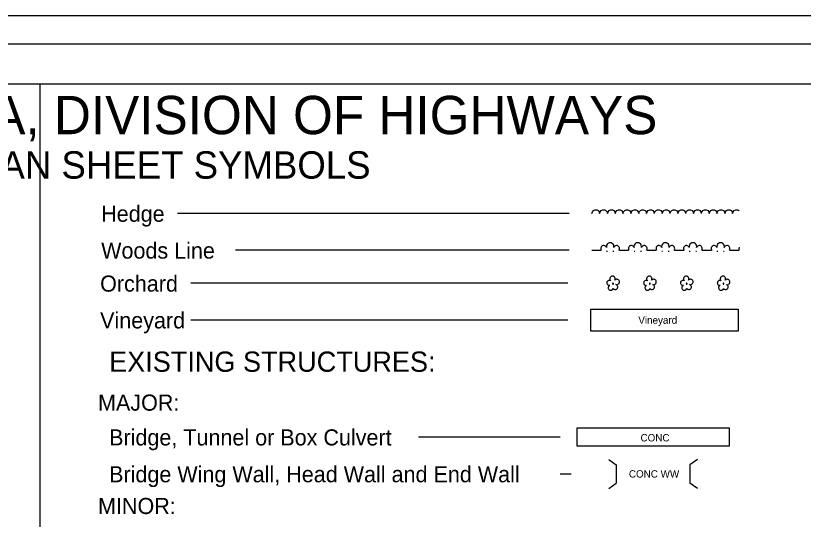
# Model space of a CAD drawing. Extents: x 811508 to 813252, y 647626 to 648754.
# Drawn here: x 812366.5 to 812809.2, y 648471 to 648754 of the extents above; entities that cross this region are included whole.
import ezdxf

# ---------------------------------------------------------------- set-up
doc = ezdxf.new("R2010")
doc.units = 0
for name, color, linetype in [('Sheet Cutting Line CELL', 7, 'Continuous'), ('Sheet Plot Border Inside CELL', 7, 'Continuous'), ('Sheet Plot Border Outside CELL', 7, 'Continuous'), ('Sheet_Plan', 7, 'Continuous'), ('Sheet_Symbology', 7, 'Continuous'), ('z - Construction', 7, 'Continuous')]:
    doc.layers.add(name, color=color, linetype=linetype)

msp = doc.modelspace()

# ---------------------------------------------------------------- linework, layer by layer
at = {"layer": 'Sheet Cutting Line CELL'}
msp.add_line((813217.6, 648737.99), (811533.6, 648737.99), dxfattribs=at)
at = {"layer": 'Sheet Plot Border Inside CELL'}
msp.add_lwpolyline([(811546.6, 647660.44), (813213.1, 647660.44), (813213.1, 648715.54), (811546.6, 648715.54)], close=True, dxfattribs=at)
at = {"layer": 'Sheet Plot Border Outside CELL'}
msp.add_lwpolyline([(811533.6, 647637.99), (813217.6, 647637.99), (813217.6, 648737.99), (811533.6, 648737.99)], close=True, dxfattribs=at)
at = {"layer": 'Sheet_Plan'}
msp.add_line((813213.53, 648715.54), (811546.6, 648715.54), dxfattribs=at)
at = {"layer": 'Sheet_Symbology'}
for p, q in [((812677.52, 648642.89), (812457.4, 648642.89)), ((812690.35, 648642.89), (812690.66, 648643.87)), ((812690.66, 648643.87), (812691.28, 648644.55)), ((812691.28, 648644.55), (812692.11, 648645.01)), ((812692.11, 648645.01), (812693.09, 648645.01)), ((812693.09, 648645.01), (812693.92, 648644.5)), ((812693.92, 648644.5), (812694.49, 648643.82)), ((812694.49, 648643.82), (812694.7, 648642.94)), ((812694.75, 648642.89), (812695.06, 648643.87)), ((812695.06, 648643.87), (812695.68, 648644.55)), ((812695.68, 648644.55), (812696.51, 648645.01)), ((812696.51, 648645.01), (812697.49, 648645.01)), ((812697.49, 648645.01), (812698.32, 648644.5)), ((812698.32, 648644.5), (812698.89, 648643.82)), ((812698.89, 648643.82), (812699.09, 648642.94)), ((812699.15, 648642.89), (812699.46, 648643.87)), ((812699.46, 648643.87), (812700.08, 648644.55)), ((812700.08, 648644.55), (812700.9, 648645.01)), ((812700.9, 648645.01), (812701.89, 648645.01)), ((812701.89, 648645.01), (812702.72, 648644.5)), ((812702.72, 648644.5), (812703.29, 648643.82)), ((812703.29, 648643.82), (812703.49, 648642.94)), ((812703.54, 648642.89), (812703.85, 648643.87)), ((812703.85, 648643.87), (812704.48, 648644.55)), ((812704.48, 648644.55), (812705.3, 648645.01)), ((812705.3, 648645.01), (812706.29, 648645.01)), ((812706.29, 648645.01), (812707.11, 648644.5)), ((812707.11, 648644.5), (812707.68, 648643.82)), ((812707.68, 648643.82), (812707.89, 648642.94)), ((812707.94, 648642.89), (812708.25, 648643.87)), ((812708.25, 648643.87), (812708.87, 648644.55)), ((812708.87, 648644.55), (812709.7, 648645.01)), ((812709.7, 648645.01), (812710.69, 648645.01)), ((812710.69, 648645.01), (812711.51, 648644.5)), ((812711.51, 648644.5), (812712.08, 648643.82)), ((812712.08, 648643.82), (812712.29, 648642.94)), ((812712.34, 648642.89), (812712.65, 648643.87)), ((812712.65, 648643.87), (812713.27, 648644.55)), ((812713.27, 648644.55), (812714.1, 648645.01)), ((812714.1, 648645.01), (812715.08, 648645.01)), ((812715.08, 648645.01), (812715.91, 648644.5)), ((812715.91, 648644.5), (812716.48, 648643.82)), ((812716.48, 648643.82), (812716.69, 648642.94)), ((812716.74, 648642.89), (812717.05, 648643.87)), ((812717.05, 648643.87), (812717.67, 648644.55)), ((812717.67, 648644.55), (812718.5, 648645.01)), ((812718.5, 648645.01), (812719.48, 648645.01)), ((812719.48, 648645.01), (812720.31, 648644.5)), ((812720.31, 648644.5), (812720.88, 648643.82)), ((812720.88, 648643.82), (812721.09, 648642.94)), ((812721.14, 648642.89), (812721.45, 648643.87)), ((812721.45, 648643.87), (812722.07, 648644.55)), ((812722.07, 648644.55), (812722.9, 648645.01)), ((812722.9, 648645.01), (812723.88, 648645.01)), ((812723.88, 648645.01), (812724.71, 648644.5)), ((812724.71, 648644.5), (812725.28, 648643.82)), ((812725.28, 648643.82), (812725.49, 648642.94)), ((812725.54, 648642.89), (812725.85, 648643.87)), ((812725.85, 648643.87), (812726.47, 648644.55)), ((812726.47, 648644.55), (812727.3, 648645.01)), ((812727.3, 648645.01), (812728.28, 648645.01)), ((812728.28, 648645.01), (812729.11, 648644.5)), ((812729.11, 648644.5), (812729.68, 648643.82)), ((812729.68, 648643.82), (812729.88, 648642.94)), ((812729.94, 648642.89), (812730.25, 648643.87)), ((812730.25, 648643.87), (812730.87, 648644.55)), ((812730.87, 648644.55), (812731.7, 648645.01)), ((812731.7, 648645.01), (812732.68, 648645.01)), ((812732.68, 648645.01), (812733.51, 648644.5)), ((812733.51, 648644.5), (812734.08, 648643.82)), ((812734.08, 648643.82), (812734.28, 648642.94)), ((812734.33, 648642.89), (812734.64, 648643.87)), ((812734.64, 648643.87), (812735.27, 648644.55)), ((812735.27, 648644.55), (812736.09, 648645.01)), ((812736.09, 648645.01), (812737.08, 648645.01)), ((812737.08, 648645.01), (812737.9, 648644.5)), ((812737.9, 648644.5), (812738.47, 648643.82)), ((812738.47, 648643.82), (812738.68, 648642.94)), ((812738.73, 648642.89), (812739.04, 648643.87)), ((812739.04, 648643.87), (812739.66, 648644.55)), ((812739.66, 648644.55), (812740.49, 648645.01)), ((812740.49, 648645.01), (812741.48, 648645.01)), ((812741.48, 648645.01), (812742.3, 648644.5)), ((812742.3, 648644.5), (812742.87, 648643.82)), ((812742.87, 648643.82), (812743.08, 648642.94)), ((812743.13, 648642.89), (812743.44, 648643.87)), ((812743.44, 648643.87), (812744.06, 648644.55)), ((812744.06, 648644.55), (812744.89, 648645.01)), ((812744.89, 648645.01), (812745.87, 648645.01)), ((812745.87, 648645.01), (812746.7, 648644.5)), ((812746.7, 648644.5), (812747.27, 648643.82)), ((812747.27, 648643.82), (812747.48, 648642.94)), ((812747.53, 648642.89), (812747.84, 648643.87)), ((812747.84, 648643.87), (812748.46, 648644.55)), ((812748.46, 648644.55), (812749.29, 648645.01)), ((812749.29, 648645.01), (812750.27, 648645.01)), ((812750.27, 648645.01), (812751.1, 648644.5)), ((812751.1, 648644.5), (812751.67, 648643.82)), ((812751.67, 648643.82), (812751.88, 648642.94)), ((812751.93, 648642.89), (812752.24, 648643.87)), ((812752.24, 648643.87), (812752.86, 648644.55)), ((812752.86, 648644.55), (812753.69, 648645.01)), ((812753.69, 648645.01), (812754.67, 648645.01)), ((812754.67, 648645.01), (812755.5, 648644.5)), ((812755.5, 648644.5), (812756.07, 648643.82)), ((812756.07, 648643.82), (812756.28, 648642.94)), ((812756.33, 648642.89), (812756.64, 648643.87)), ((812756.64, 648643.87), (812757.26, 648644.55)), ((812757.26, 648644.55), (812758.09, 648645.01)), ((812758.09, 648645.01), (812759.07, 648645.01)), ((812759.07, 648645.01), (812759.9, 648644.5)), ((812759.9, 648644.5), (812760.47, 648643.82)), ((812760.47, 648643.82), (812760.67, 648642.94)), ((812760.73, 648642.89), (812761.04, 648643.87)), ((812761.04, 648643.87), (812761.66, 648644.55)), ((812761.66, 648644.55), (812762.49, 648645.01)), ((812762.49, 648645.01), (812763.47, 648645.01)), ((812763.47, 648645.01), (812764.3, 648644.5)), ((812764.3, 648644.5), (812764.87, 648643.82)), ((812764.87, 648643.82), (812765.07, 648642.94)), ((812765.12, 648642.89), (812765.44, 648643.87)), ((812765.44, 648643.87), (812766.06, 648644.55)), ((812766.06, 648644.55), (812766.88, 648645.01)), ((812766.88, 648645.01), (812767.87, 648645.01)), ((812767.87, 648645.01), (812768.7, 648644.5)), ((812768.7, 648644.5), (812769.26, 648643.82)), ((812769.26, 648643.82), (812769.47, 648642.94)), ((812769.52, 648642.89), (812769.83, 648643.87)), ((812769.83, 648643.87), (812770.45, 648644.55)), ((812770.45, 648644.55), (812771.28, 648645.01)), ((812771.28, 648645.01), (812772.27, 648645.01)), ((812772.27, 648645.01), (812773.09, 648644.5)), ((812773.09, 648644.5), (812773.15, 648644.44)), ((812677.52, 648622.19), (812490.06, 648622.19)), ((812690.35, 648622.19), (812695.52, 648622.19)), ((812698.58, 648621.67), (812699.09, 648621.67)), ((812702.2, 648621.67), (812702.72, 648621.67)), ((812705.87, 648622.19), (812711.05, 648622.19)), ((812714.1, 648621.67), (812714.62, 648621.67)), ((812717.72, 648621.67), (812718.24, 648621.67)), ((812721.4, 648622.19), (812726.57, 648622.19)), ((812729.63, 648621.67), (812730.14, 648621.67)), ((812733.25, 648621.67), (812733.77, 648621.67)), ((812736.92, 648622.19), (812742.1, 648622.19)), ((812745.15, 648621.67), (812745.67, 648621.67)), ((812748.77, 648621.67), (812749.29, 648621.67)), ((812752.45, 648622.19), (812757.62, 648622.19)), ((812760.67, 648621.67), (812761.19, 648621.67)), ((812764.3, 648621.67), (812764.81, 648621.67)), ((812767.97, 648622.19), (812773.15, 648622.19)), ((812676.94, 648603.64), (812464.83, 648603.64)), ((812676.94, 648582.94), (812464.83, 648582.94)), ((812672.47, 648517.21), (812592.81, 648517.21)), ((812699.85, 648504.65), (812704.09, 648501.69)), ((812704.09, 648501.69), (812704.09, 648491.34)), ((812749.73, 648504.65), (812745.49, 648501.69)), ((812745.49, 648501.69), (812745.49, 648491.34)), ((812672.47, 648496.51), (812678.67, 648496.51)), ((812699.85, 648488.38), (812704.09, 648491.34)), ((812749.73, 648488.38), (812745.49, 648491.34))]:
    msp.add_line(p, q, dxfattribs=at)
for points in [[(812703.27, 648605.45), (812703.42, 648605.76), (812703.48, 648606.07), (812703.42, 648606.38), (812703.37, 648606.69), (812703.22, 648606.95), (812703.06, 648607.21), (812702.8, 648607.42), (812702.54, 648607.57), (812702.18, 648607.67), (812701.92, 648607.67), (812701.61, 648607.62), (812701.3, 648607.52), (812701.04, 648607.36), (812700.79, 648607.16), (812700.63, 648606.85), (812700.53, 648606.59), (812700.48, 648606.28), (812700.48, 648605.97), (812700.53, 648605.66), (812700.68, 648605.4), (812700.89, 648605.09), (812700.63, 648605.24), (812700.32, 648605.29), (812700.01, 648605.29), (812699.75, 648605.19), (812699.49, 648605.09), (812699.23, 648604.88), (812699.03, 648604.67), (812698.87, 648604.41), (812698.82, 648604.16), (812698.77, 648603.79), (812698.82, 648603.53), (812698.92, 648603.28), (812699.13, 648603.02), (812699.28, 648602.81), (812699.54, 648602.65), (812699.85, 648602.5), (812700.11, 648602.45), (812700.42, 648602.45), (812700.16, 648602.34), (812699.91, 648602.14), (812699.75, 648601.93), (812699.65, 648601.62), (812699.54, 648601.31), (812699.54, 648601.05), (812699.6, 648600.74), (812699.75, 648600.48), (812699.91, 648600.22), (812700.11, 648600.02), (812700.37, 648599.86), (812700.63, 648599.76), (812700.94, 648599.76), (812701.25, 648599.76), (812701.51, 648599.81), (812701.77, 648600.02), (812702.03, 648600.17), (812702.29, 648600.64)], [(812723.97, 648605.45), (812724.12, 648605.76), (812724.18, 648606.07), (812724.12, 648606.38), (812724.07, 648606.69), (812723.92, 648606.95), (812723.76, 648607.21), (812723.5, 648607.42), (812723.24, 648607.57), (812722.88, 648607.67), (812722.62, 648607.67), (812722.31, 648607.62), (812722, 648607.52), (812721.74, 648607.36), (812721.48, 648607.16), (812721.33, 648606.85), (812721.23, 648606.59), (812721.17, 648606.28), (812721.17, 648605.97), (812721.23, 648605.66), (812721.38, 648605.4), (812721.59, 648605.09), (812721.33, 648605.24), (812721.02, 648605.29), (812720.71, 648605.29), (812720.45, 648605.19), (812720.19, 648605.09), (812719.93, 648604.88), (812719.73, 648604.67), (812719.57, 648604.41), (812719.52, 648604.16), (812719.47, 648603.79), (812719.52, 648603.53), (812719.62, 648603.28), (812719.83, 648603.02), (812719.98, 648602.81), (812720.24, 648602.65), (812720.55, 648602.5), (812720.81, 648602.45), (812721.12, 648602.45), (812720.86, 648602.34), (812720.61, 648602.14), (812720.45, 648601.93), (812720.35, 648601.62), (812720.24, 648601.31), (812720.24, 648601.05), (812720.29, 648600.74), (812720.45, 648600.48), (812720.61, 648600.22), (812720.81, 648600.02), (812721.07, 648599.86), (812721.33, 648599.76), (812721.64, 648599.76), (812721.95, 648599.76), (812722.21, 648599.81), (812722.47, 648600.02), (812722.73, 648600.17), (812722.99, 648600.64)], [(812744.67, 648605.45), (812744.82, 648605.76), (812744.88, 648606.07), (812744.82, 648606.38), (812744.77, 648606.69), (812744.62, 648606.95), (812744.46, 648607.21), (812744.2, 648607.42), (812743.94, 648607.57), (812743.58, 648607.67), (812743.32, 648607.67), (812743.01, 648607.62), (812742.7, 648607.52), (812742.44, 648607.36), (812742.18, 648607.16), (812742.03, 648606.85), (812741.93, 648606.59), (812741.87, 648606.28), (812741.87, 648605.97), (812741.93, 648605.66), (812742.08, 648605.4), (812742.29, 648605.09), (812742.03, 648605.24), (812741.72, 648605.29), (812741.41, 648605.29), (812741.15, 648605.19), (812740.89, 648605.09), (812740.63, 648604.88), (812740.42, 648604.67), (812740.27, 648604.41), (812740.22, 648604.16), (812740.17, 648603.79), (812740.22, 648603.53), (812740.32, 648603.28), (812740.53, 648603.02), (812740.68, 648602.81), (812740.94, 648602.65), (812741.25, 648602.5), (812741.51, 648602.45), (812741.82, 648602.45), (812741.56, 648602.34), (812741.3, 648602.14), (812741.15, 648601.93), (812741.05, 648601.62), (812740.94, 648601.31), (812740.94, 648601.05), (812740.99, 648600.74), (812741.15, 648600.48), (812741.3, 648600.22), (812741.51, 648600.02), (812741.77, 648599.86), (812742.03, 648599.76), (812742.34, 648599.76), (812742.65, 648599.76), (812742.91, 648599.81), (812743.17, 648600.02), (812743.43, 648600.17), (812743.68, 648600.64)], [(812765.37, 648605.45), (812765.52, 648605.76), (812765.57, 648606.07), (812765.52, 648606.38), (812765.47, 648606.69), (812765.32, 648606.95), (812765.16, 648607.21), (812764.9, 648607.42), (812764.64, 648607.57), (812764.28, 648607.67), (812764.02, 648607.67), (812763.71, 648607.62), (812763.4, 648607.52), (812763.14, 648607.36), (812762.88, 648607.16), (812762.73, 648606.85), (812762.62, 648606.59), (812762.57, 648606.28), (812762.57, 648605.97), (812762.62, 648605.66), (812762.78, 648605.4), (812762.99, 648605.09), (812762.73, 648605.24), (812762.42, 648605.29), (812762.11, 648605.29), (812761.85, 648605.19), (812761.59, 648605.09), (812761.33, 648604.88), (812761.12, 648604.67), (812760.97, 648604.41), (812760.92, 648604.16), (812760.87, 648603.79), (812760.92, 648603.53), (812761.02, 648603.28), (812761.23, 648603.02), (812761.38, 648602.81), (812761.64, 648602.65), (812761.95, 648602.5), (812762.21, 648602.45), (812762.52, 648602.45), (812762.26, 648602.34), (812762, 648602.14), (812761.85, 648601.93), (812761.75, 648601.62), (812761.64, 648601.31), (812761.64, 648601.05), (812761.69, 648600.74), (812761.85, 648600.48), (812762, 648600.22), (812762.21, 648600.02), (812762.47, 648599.86), (812762.73, 648599.76), (812763.04, 648599.76), (812763.35, 648599.76), (812763.61, 648599.81), (812763.87, 648600.02), (812764.13, 648600.17), (812764.38, 648600.64)], [(812702.39, 648603.64), (812702.23, 648603.64), (812702.13, 648603.59), (812702.03, 648603.53), (812702.03, 648603.38), (812702.03, 648603.28), (812702.13, 648603.17), (812702.29, 648603.17), (812702.39, 648603.17), (812702.49, 648603.28), (812702.54, 648603.43), (812702.49, 648603.53), (812702.39, 648603.64)], [(812702.29, 648600.64), (812702.91, 648600.27), (812703.22, 648600.17), (812703.53, 648600.12), (812703.84, 648600.17), (812704.1, 648600.27), (812704.36, 648600.43), (812704.61, 648600.64), (812704.77, 648600.9), (812704.87, 648601.15), (812704.98, 648601.46), (812704.93, 648601.77), (812704.87, 648602.09), (812704.67, 648602.4), (812704.51, 648602.6), (812704.25, 648602.76), (812703.94, 648602.91), (812704.25, 648602.86), (812704.61, 648602.86), (812704.87, 648602.97), (812705.18, 648603.12), (812705.44, 648603.28), (812705.65, 648603.53), (812705.81, 648603.84), (812705.86, 648604.16), (812705.91, 648604.47), (812705.86, 648604.78), (812705.75, 648605.09), (812705.55, 648605.35), (812705.29, 648605.6), (812705.03, 648605.76), (812704.72, 648605.86), (812704.41, 648605.91), (812704.1, 648605.91), (812703.79, 648605.81), (812703.53, 648605.66), (812703.27, 648605.45)], [(812723.09, 648603.64), (812722.93, 648603.64), (812722.83, 648603.59), (812722.73, 648603.53), (812722.73, 648603.38), (812722.73, 648603.28), (812722.83, 648603.17), (812722.99, 648603.17), (812723.09, 648603.17), (812723.19, 648603.28), (812723.24, 648603.43), (812723.19, 648603.53), (812723.09, 648603.64)], [(812722.99, 648600.64), (812723.61, 648600.27), (812723.92, 648600.17), (812724.23, 648600.12), (812724.54, 648600.17), (812724.8, 648600.27), (812725.06, 648600.43), (812725.31, 648600.64), (812725.47, 648600.9), (812725.57, 648601.15), (812725.68, 648601.46), (812725.62, 648601.77), (812725.57, 648602.09), (812725.37, 648602.4), (812725.21, 648602.6), (812724.95, 648602.76), (812724.64, 648602.91), (812724.95, 648602.86), (812725.31, 648602.86), (812725.57, 648602.97), (812725.88, 648603.12), (812726.14, 648603.28), (812726.35, 648603.53), (812726.5, 648603.84), (812726.56, 648604.16), (812726.61, 648604.47), (812726.56, 648604.78), (812726.45, 648605.09), (812726.25, 648605.35), (812725.99, 648605.6), (812725.73, 648605.76), (812725.42, 648605.86), (812725.11, 648605.91), (812724.8, 648605.91), (812724.49, 648605.81), (812724.23, 648605.66), (812723.97, 648605.45)], [(812743.79, 648603.64), (812743.63, 648603.64), (812743.53, 648603.59), (812743.43, 648603.53), (812743.43, 648603.38), (812743.43, 648603.28), (812743.53, 648603.17), (812743.68, 648603.17), (812743.79, 648603.17), (812743.89, 648603.28), (812743.94, 648603.43), (812743.89, 648603.53), (812743.79, 648603.64)], [(812743.68, 648600.64), (812744.31, 648600.27), (812744.62, 648600.17), (812744.93, 648600.12), (812745.24, 648600.17), (812745.5, 648600.27), (812745.75, 648600.43), (812746.01, 648600.64), (812746.17, 648600.9), (812746.27, 648601.15), (812746.38, 648601.46), (812746.32, 648601.77), (812746.27, 648602.09), (812746.07, 648602.4), (812745.91, 648602.6), (812745.65, 648602.76), (812745.34, 648602.91), (812745.65, 648602.86), (812746.01, 648602.86), (812746.27, 648602.97), (812746.58, 648603.12), (812746.84, 648603.28), (812747.05, 648603.53), (812747.2, 648603.84), (812747.26, 648604.16), (812747.31, 648604.47), (812747.26, 648604.78), (812747.15, 648605.09), (812746.95, 648605.35), (812746.69, 648605.6), (812746.43, 648605.76), (812746.12, 648605.86), (812745.81, 648605.91), (812745.5, 648605.91), (812745.19, 648605.81), (812744.93, 648605.66), (812744.67, 648605.45)], [(812764.49, 648603.64), (812764.33, 648603.64), (812764.23, 648603.59), (812764.13, 648603.53), (812764.13, 648603.38), (812764.13, 648603.28), (812764.23, 648603.17), (812764.38, 648603.17), (812764.49, 648603.17), (812764.59, 648603.28), (812764.64, 648603.43), (812764.59, 648603.53), (812764.49, 648603.64)], [(812764.38, 648600.64), (812765.01, 648600.27), (812765.32, 648600.17), (812765.63, 648600.12), (812765.94, 648600.17), (812766.2, 648600.27), (812766.45, 648600.43), (812766.71, 648600.64), (812766.87, 648600.9), (812766.97, 648601.15), (812767.08, 648601.46), (812767.02, 648601.77), (812766.97, 648602.09), (812766.76, 648602.4), (812766.61, 648602.6), (812766.35, 648602.76), (812766.04, 648602.91), (812766.35, 648602.86), (812766.71, 648602.86), (812766.97, 648602.97), (812767.28, 648603.12), (812767.54, 648603.28), (812767.75, 648603.53), (812767.9, 648603.84), (812767.95, 648604.16), (812768.01, 648604.47), (812767.95, 648604.78), (812767.85, 648605.09), (812767.64, 648605.35), (812767.39, 648605.6), (812767.13, 648605.76), (812766.82, 648605.86), (812766.51, 648605.91), (812766.2, 648605.91), (812765.89, 648605.81), (812765.63, 648605.66), (812765.37, 648605.45)], [(812689.76, 648589.15), (812772.56, 648589.15), (812772.56, 648576.73), (812689.76, 648576.73), (812689.76, 648589.15)], [(812682.1, 648522.39), (812767.48, 648522.39), (812767.48, 648512.04), (812682.1, 648512.04), (812682.1, 648522.39)]]:
    msp.add_lwpolyline(points, dxfattribs=at)
for centre, radius, start, end in [((812700.65, 648624.28), 2.13, 345.9638, 194.0362), ((812716.17, 648624.28), 2.13, 345.9638, 194.0362), ((812731.69, 648624.28), 2.13, 345.9638, 194.0362), ((812747.22, 648624.28), 2.13, 345.9638, 194.0362), ((812762.74, 648624.28), 2.13, 345.9638, 194.0362), ((812697.02, 648623.24), 1.64, 18.435, 219.2315), ((812704.27, 648623.24), 1.64, 320.7685, 161.5651), ((812712.55, 648623.24), 1.64, 18.435, 219.2315), ((812719.79, 648623.24), 1.64, 320.7685, 161.5651), ((812728.07, 648623.24), 1.64, 18.435, 219.2315), ((812735.31, 648623.24), 1.64, 320.7685, 161.5651), ((812743.59, 648623.24), 1.64, 18.435, 219.2315), ((812750.84, 648623.24), 1.64, 320.7685, 161.5651), ((812759.12, 648623.24), 1.64, 18.435, 219.2315), ((812766.36, 648623.24), 1.64, 320.7685, 161.5651), ((812774.64, 648623.24), 1.64, 156.251, 203.749)]:
    msp.add_arc(centre, radius, start, end, dxfattribs=at)
at = {"layer": 'z - Construction'}
for p, q in [((813251.99, 648754), (811508.14, 648754)), ((812380.06, 648715.54), (812380.04, 647664.09))]:
    msp.add_line(p, q, dxfattribs=at)

# ---------------------------------------------------------------- texts
at = {"layer": 'Sheet_Symbology'}
for s, height, p in [('STATE OF NORTH CAROLINA, DIVISION OF HIGHWAYS', 21.5418, (811965.38, 648687.44)), ('CONVENTIONAL  PLAN SHEET SYMBOLS', 15.387, (812158.9, 648662.45)), ('Hedge', 9.056, (812414.47, 648638.21)), ('Woods Line', 9.056, (812414.47, 648617.51)), ('Orchard', 9.056, (812413.89, 648598.95)), ('Vineyard', 9.056, (812413.89, 648578.26)), ('EXISTING STRUCTURES:', 11.3847, (812418.94, 648553.9)), ('MAJOR:', 9.056, (812412.71, 648532.05)), ('Bridge, Tunnel or Box Culvert', 9.056, (812418.94, 648512.5)), ('CONC', 4.14, (812717.74, 648514.77)), ('Bridge Wing Wall, Head Wall and End Wall', 9.056, (812418.94, 648491.8)), ('MINOR:', 9.056, (812412.71, 648473.96))]:
    msp.add_text(s, height=height, dxfattribs=at).set_placement(p)
for s, p in [('Vineyard', (812716.49, 648580.87)), ('CONC WW', (812711.2, 648494.44))]:
    msp.add_text(s, height=4.14, rotation=0, dxfattribs=at).set_placement(p)

doc.saveas('drawing.dxf')
